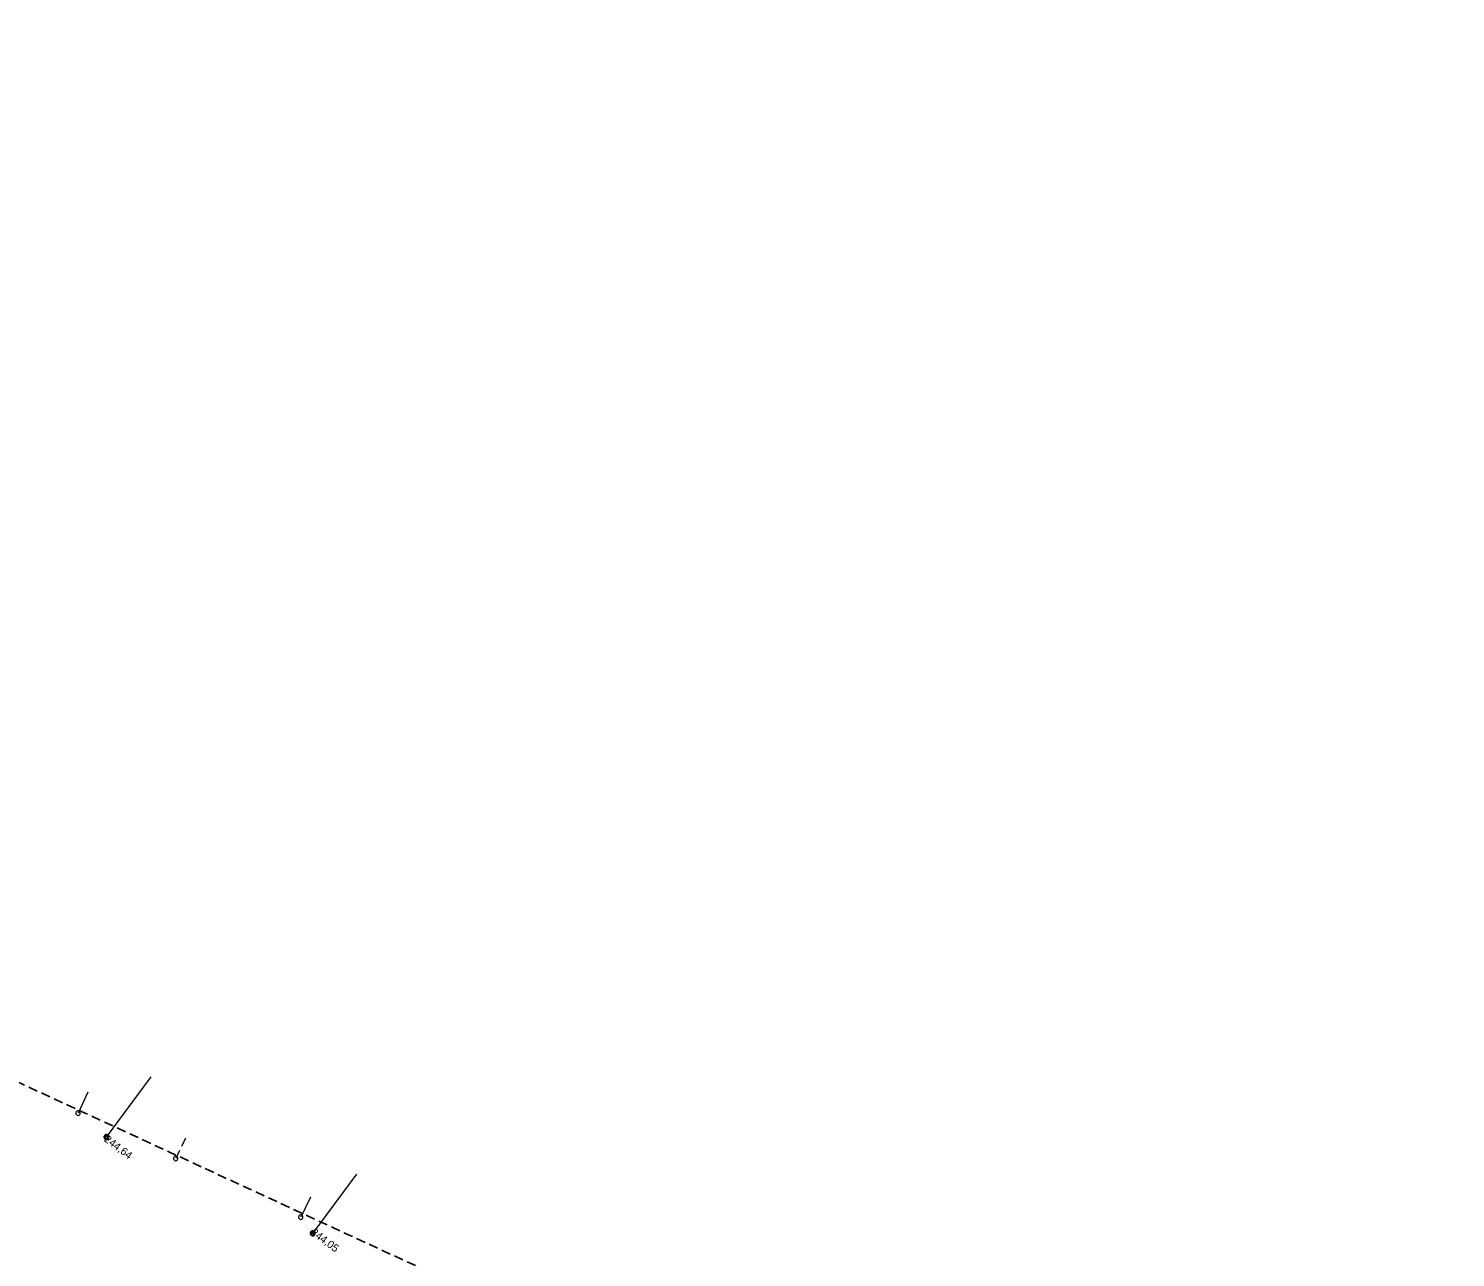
# Model space of a CAD drawing. Extents: x -735085 to -733500, y -1044153 to -1043402.
# Drawn here: x -734443.8 to -734295.8, y -1043690.4 to -1043562.9 of the extents above; entities that cross this region are included whole.
import ezdxf

# ---------------------------------------------------------------- set-up
doc = ezdxf.new("R2010")
doc.units = 0
doc.header["$LTSCALE"] = 0.32
doc.linetypes.add('MEDIUM_DASHED', pattern=[4.5, 3, -1.5])
doc.layers.add('16', color=7, linetype='Continuous')
for name, color, linetype, lineweight in [('18', 7, 'Continuous', 13), ('49', 7, 'Continuous', 13), ('63', 7, 'MEDIUM_DASHED', 25), ('8', 7, 'Continuous', 13)]:
    doc.layers.add(name, color=color, linetype=linetype, lineweight=lineweight)

msp = doc.modelspace()

# ---------------------------------------------------------------- linework, layer by layer
at = {"layer": '18'}
for points in [[(-734435.437, -1043677.871), (-734435.443, -1043677.815), (-734435.46, -1043677.762), (-734435.489, -1043677.713), (-734435.527, -1043677.672), (-734435.573, -1043677.64), (-734435.625, -1043677.618), (-734435.68, -1043677.607), (-734435.736, -1043677.609), (-734435.791, -1043677.622), (-734435.842, -1043677.647), (-734435.886, -1043677.682), (-734435.922, -1043677.725), (-734435.947, -1043677.775), (-734435.962, -1043677.83), (-734435.965, -1043677.886), (-734435.956, -1043677.941), (-734435.935, -1043677.994), (-734435.904, -1043678.04), (-734435.864, -1043678.079), (-734435.816, -1043678.109), (-734435.763, -1043678.128), (-734435.707, -1043678.135), (-734435.651, -1043678.131), (-734435.597, -1043678.114), (-734435.548, -1043678.087), (-734435.506, -1043678.049), (-734435.473, -1043678.004), (-734435.45, -1043677.953), (-734435.438, -1043677.898)], [(-734435.496, -1043677.874), (-734435.502, -1043677.825), (-734435.52, -1043677.779), (-734435.548, -1043677.738), (-734435.585, -1043677.705), (-734435.629, -1043677.683), (-734435.677, -1043677.671), (-734435.726, -1043677.671), (-734435.774, -1043677.683), (-734435.818, -1043677.706), (-734435.855, -1043677.739), (-734435.883, -1043677.78), (-734435.9, -1043677.827), (-734435.906, -1043677.876), (-734435.899, -1043677.925), (-734435.881, -1043677.971), (-734435.853, -1043678.011), (-734435.816, -1043678.044), (-734435.772, -1043678.066), (-734435.723, -1043678.078), (-734435.674, -1043678.077), (-734435.626, -1043678.065), (-734435.583, -1043678.041), (-734435.546, -1043678.008), (-734435.518, -1043677.967), (-734435.502, -1043677.92)], [(-734435.555, -1043677.878), (-734435.561, -1043677.836), (-734435.578, -1043677.798), (-734435.606, -1043677.767), (-734435.641, -1043677.744), (-734435.681, -1043677.733), (-734435.723, -1043677.733), (-734435.763, -1043677.745), (-734435.798, -1043677.768), (-734435.825, -1043677.8), (-734435.842, -1043677.838), (-734435.847, -1043677.879), (-734435.841, -1043677.921), (-734435.823, -1043677.958), (-734435.795, -1043677.99), (-734435.759, -1043678.012), (-734435.719, -1043678.023), (-734435.677, -1043678.022), (-734435.637, -1043678.009), (-734435.603, -1043677.986), (-734435.576, -1043677.953), (-734435.56, -1043677.915)], [(-734414.047, -1043687.855), (-734414.053, -1043687.799), (-734414.07, -1043687.746), (-734414.098, -1043687.697), (-734414.137, -1043687.656), (-734414.183, -1043687.624), (-734414.235, -1043687.602), (-734414.29, -1043687.591), (-734414.346, -1043687.593), (-734414.401, -1043687.606), (-734414.451, -1043687.631), (-734414.496, -1043687.666), (-734414.532, -1043687.709), (-734414.557, -1043687.759), (-734414.572, -1043687.814), (-734414.575, -1043687.87), (-734414.566, -1043687.925), (-734414.545, -1043687.978), (-734414.514, -1043688.024), (-734414.473, -1043688.063), (-734414.426, -1043688.093), (-734414.373, -1043688.112), (-734414.317, -1043688.119), (-734414.261, -1043688.115), (-734414.206, -1043688.098), (-734414.157, -1043688.071), (-734414.116, -1043688.033), (-734414.083, -1043687.988), (-734414.059, -1043687.937), (-734414.048, -1043687.882)], [(-734414.106, -1043687.858), (-734414.112, -1043687.809), (-734414.13, -1043687.763), (-734414.157, -1043687.722), (-734414.195, -1043687.689), (-734414.239, -1043687.667), (-734414.287, -1043687.655), (-734414.336, -1043687.655), (-734414.384, -1043687.667), (-734414.428, -1043687.69), (-734414.465, -1043687.723), (-734414.493, -1043687.764), (-734414.51, -1043687.811), (-734414.516, -1043687.86), (-734414.509, -1043687.909), (-734414.491, -1043687.955), (-734414.463, -1043687.995), (-734414.426, -1043688.028), (-734414.382, -1043688.05), (-734414.333, -1043688.062), (-734414.284, -1043688.061), (-734414.236, -1043688.049), (-734414.193, -1043688.025), (-734414.156, -1043687.992), (-734414.128, -1043687.951), (-734414.112, -1043687.904)], [(-734414.165, -1043687.862), (-734414.171, -1043687.82), (-734414.188, -1043687.782), (-734414.216, -1043687.751), (-734414.25, -1043687.728), (-734414.291, -1043687.717), (-734414.333, -1043687.717), (-734414.373, -1043687.729), (-734414.407, -1043687.752), (-734414.434, -1043687.784), (-734414.451, -1043687.822), (-734414.456, -1043687.863), (-734414.451, -1043687.905), (-734414.433, -1043687.942), (-734414.405, -1043687.974), (-734414.369, -1043687.996), (-734414.329, -1043688.007), (-734414.287, -1043688.006), (-734414.247, -1043687.993), (-734414.213, -1043687.97), (-734414.186, -1043687.937), (-734414.17, -1043687.899)]]:
    msp.add_lwpolyline(points, close=True, dxfattribs=at)
at = {"layer": '49'}
for p, q in [((-734435.701, -1043677.884), (-734431.066, -1043671.616)), ((-734435.701, -1043677.884), (-734431.066, -1043671.616)), ((-734414.311, -1043687.868), (-734409.741, -1043681.736)), ((-734414.311, -1043687.868), (-734409.741, -1043681.736))]:
    msp.add_line(p, q, dxfattribs=at)
at = {"layer": '63'}
msp.add_lwpolyline([(-734957.565, -1043435.501), (-734250.468, -1043761.931)], dxfattribs=at)
at = {"layer": '8'}
for p, q in [((-734437.629, -1043673.22), (-734438.638, -1043675.4)), ((-734414.53, -1043684.1), (-734415.546, -1043686.186))]:
    msp.add_line(p, q, dxfattribs=at)
at = {"layer": '8', "linetype": 'MEDIUM_DASHED'}
msp.add_line((-734427.5, -1043677.981), (-734428.506, -1043680.1), dxfattribs=at)
at = {"layer": '8'}
for points in [[(-734438.551, -1043675.185), (-734438.601, -1043675.169), (-734438.654, -1043675.164), (-734438.706, -1043675.172), (-734438.755, -1043675.191), (-734438.798, -1043675.221), (-734438.834, -1043675.26), (-734438.86, -1043675.305), (-734438.875, -1043675.355), (-734438.878, -1043675.408), (-734438.869, -1043675.46), (-734438.848, -1043675.508), (-734438.818, -1043675.55), (-734438.777, -1043675.585), (-734438.731, -1043675.609), (-734438.681, -1043675.624), (-734438.628, -1043675.624), (-734438.577, -1043675.615), (-734438.528, -1043675.593), (-734438.487, -1043675.561), (-734438.454, -1043675.52), (-734438.43, -1043675.474), (-734438.418, -1043675.423), (-734438.418, -1043675.37), (-734438.43, -1043675.318), (-734438.452, -1043675.272), (-734438.485, -1043675.23), (-734438.527, -1043675.198)], [(-734428.42, -1043679.885), (-734428.47, -1043679.869), (-734428.523, -1043679.865), (-734428.575, -1043679.872), (-734428.624, -1043679.892), (-734428.667, -1043679.921), (-734428.702, -1043679.96), (-734428.728, -1043680.006), (-734428.743, -1043680.056), (-734428.746, -1043680.109), (-734428.737, -1043680.161), (-734428.715, -1043680.209), (-734428.685, -1043680.251), (-734428.645, -1043680.286), (-734428.599, -1043680.31), (-734428.548, -1043680.324), (-734428.495, -1043680.324), (-734428.444, -1043680.315), (-734428.396, -1043680.293), (-734428.355, -1043680.261), (-734428.321, -1043680.22), (-734428.298, -1043680.173), (-734428.286, -1043680.122), (-734428.286, -1043680.069), (-734428.298, -1043680.017), (-734428.321, -1043679.971), (-734428.354, -1043679.93), (-734428.396, -1043679.898)], [(-734415.454, -1043685.973), (-734415.503, -1043685.956), (-734415.556, -1043685.95), (-734415.608, -1043685.956), (-734415.658, -1043685.974), (-734415.702, -1043686.003), (-734415.738, -1043686.041), (-734415.765, -1043686.085), (-734415.782, -1043686.135), (-734415.786, -1043686.187), (-734415.778, -1043686.24), (-734415.759, -1043686.289), (-734415.73, -1043686.332), (-734415.69, -1043686.367), (-734415.645, -1043686.393), (-734415.595, -1043686.409), (-734415.542, -1043686.411), (-734415.491, -1043686.403), (-734415.442, -1043686.382), (-734415.4, -1043686.351), (-734415.365, -1043686.311), (-734415.34, -1043686.265), (-734415.327, -1043686.214), (-734415.325, -1043686.162), (-734415.336, -1043686.11), (-734415.357, -1043686.063), (-734415.389, -1043686.02), (-734415.429, -1043685.987)]]:
    msp.add_lwpolyline(points, close=True, dxfattribs=at)

# ---------------------------------------------------------------- texts
at = {"layer": '16'}
for s, p in [('244,64', (-734436.01, -1043678.254)), ('244,05', (-734414.59, -1043687.899))]:
    msp.add_text(s, height=0.8, rotation=323, dxfattribs=at).set_placement(p)

doc.saveas('drawing.dxf')
